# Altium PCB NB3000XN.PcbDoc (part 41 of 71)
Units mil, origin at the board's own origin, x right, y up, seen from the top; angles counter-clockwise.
Board outline 9527.56 x 6929.77 mil, 6 copper layers (Top Layer, GND+SHIELD, MidLayer1, MidLayer2, P2 - 3V3+5V0, Bottom Layer), stack 62.375 mil thick; 832 components, 1027 nets, 4655 pads, 4981 vias.
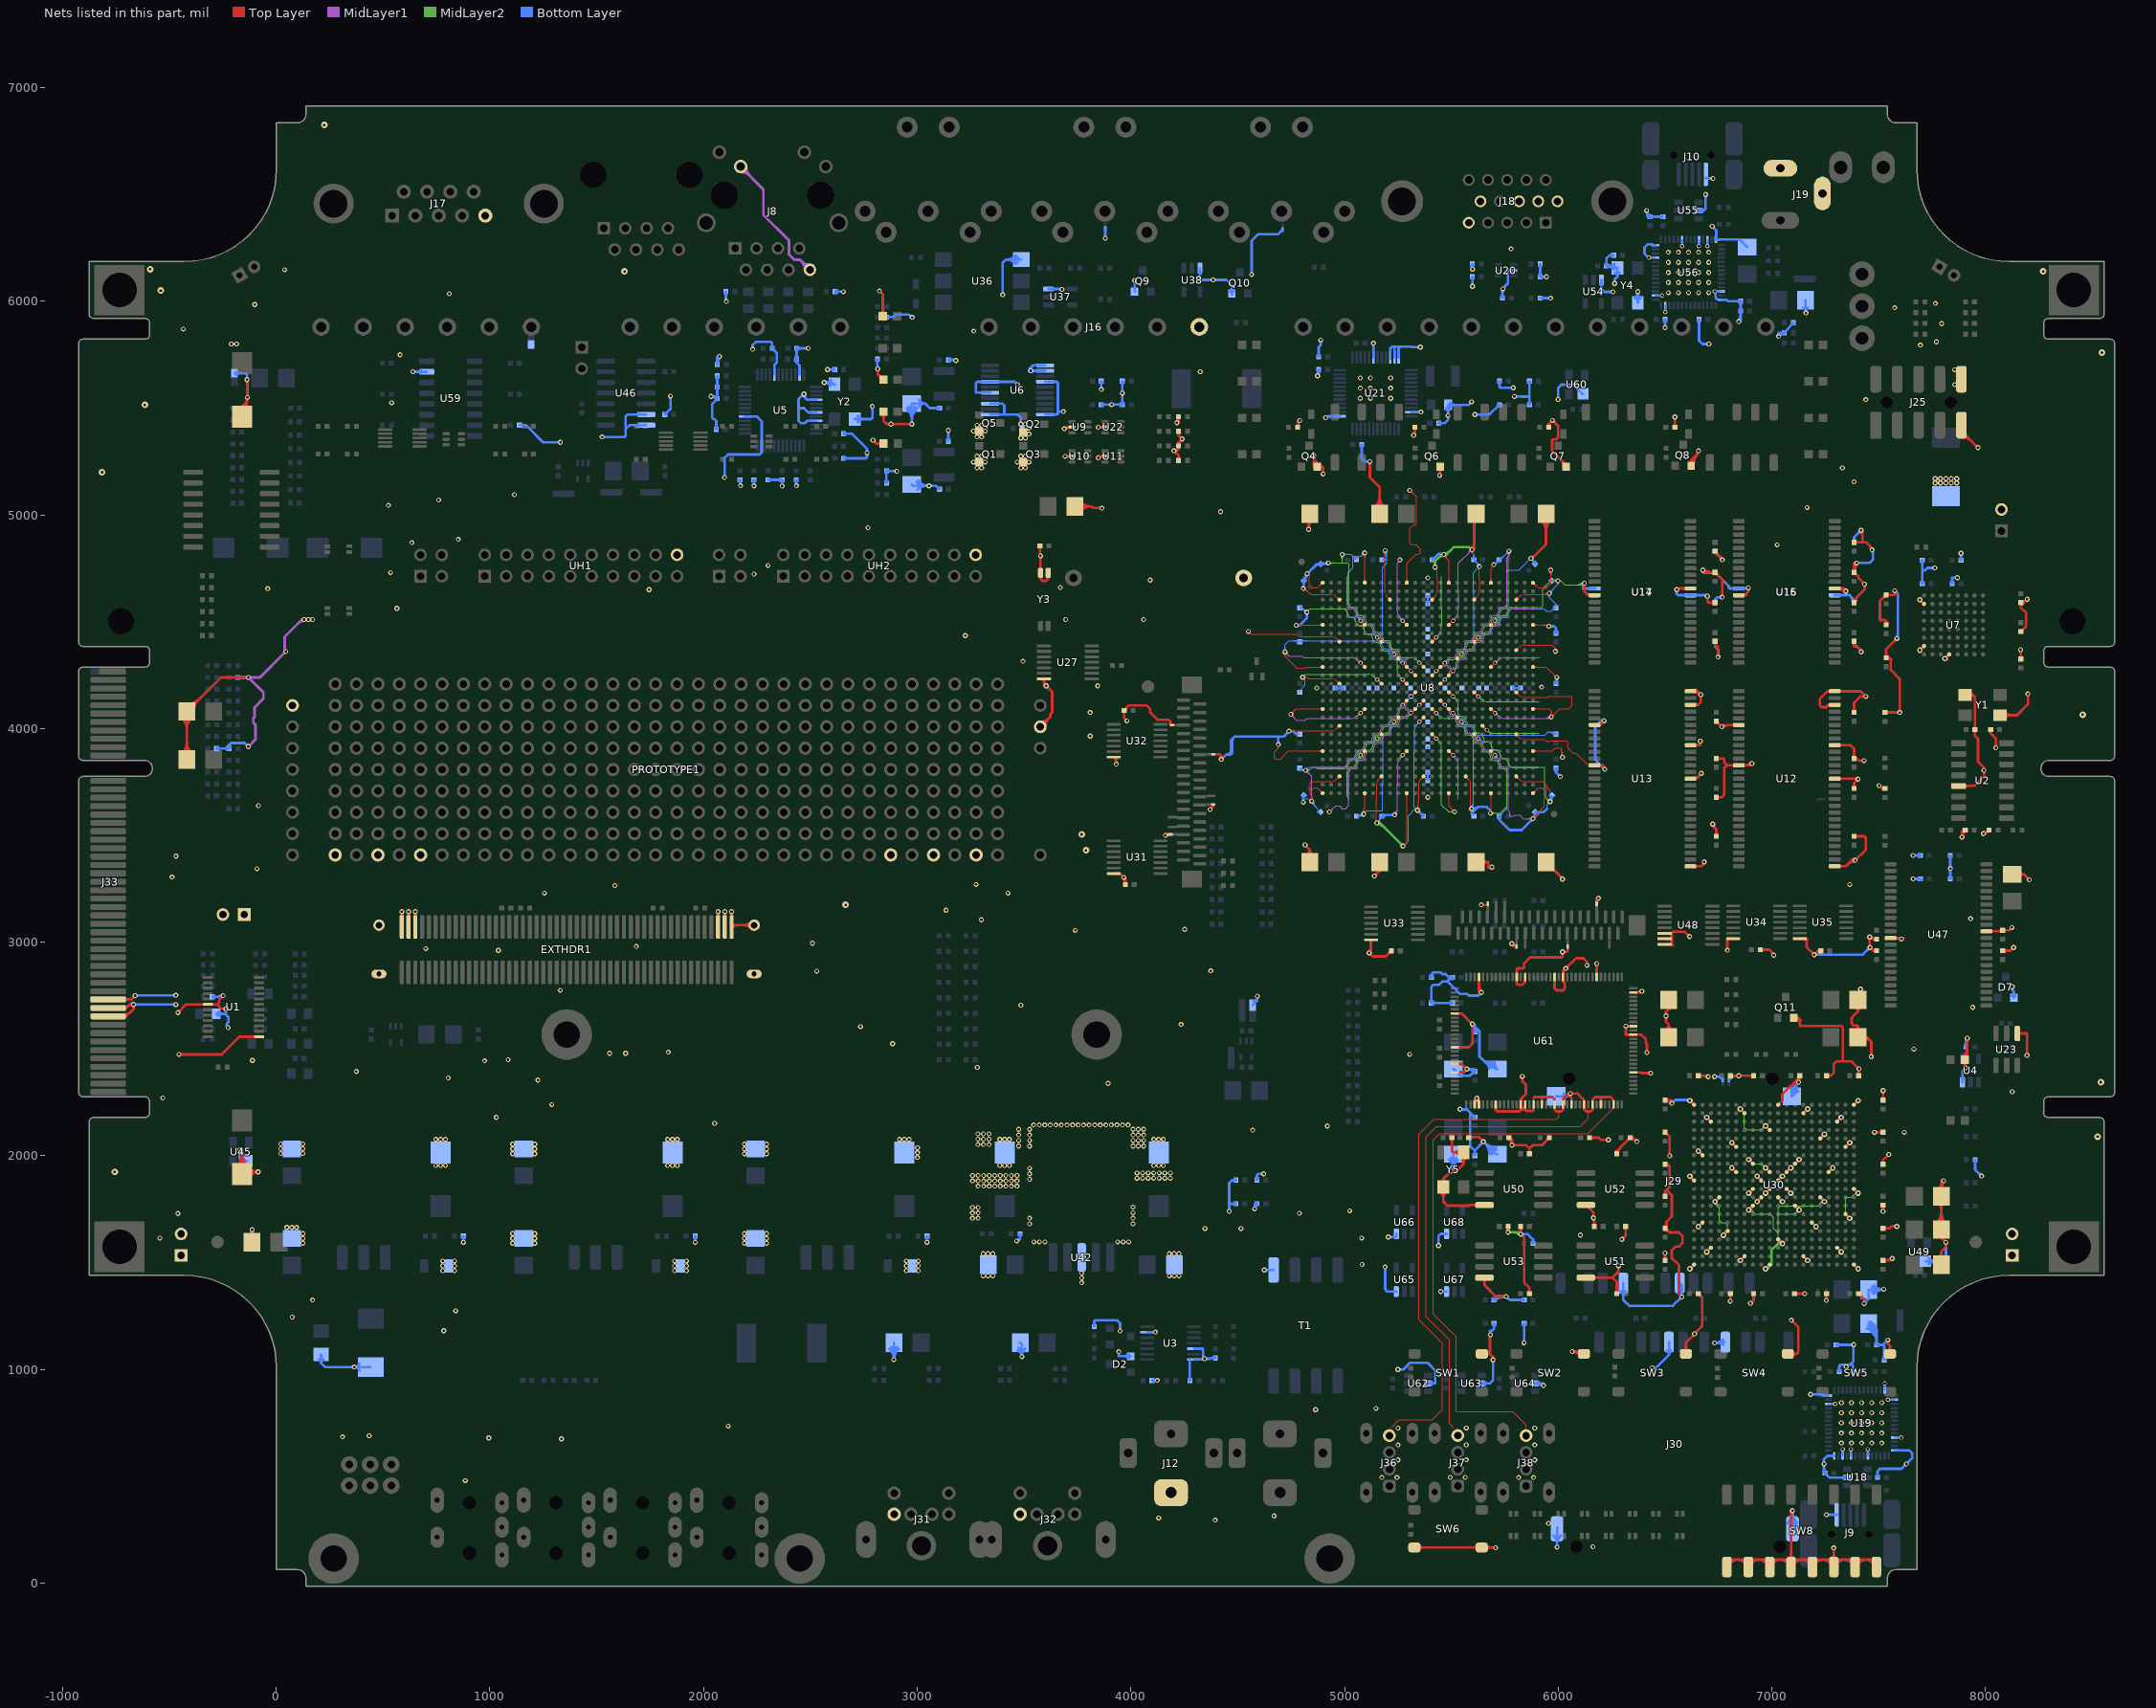
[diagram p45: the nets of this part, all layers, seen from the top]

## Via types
v1: diameter 23, hole 11.81, Top Layer to Bottom Layer, 3672 vias
v2: diameter 26, hole 11.81, Top Layer to Bottom Layer, 461 vias
v3: diameter 19, hole 11.81, Top Layer to Bottom Layer, tented both sides, 396 vias
v4: diameter 23.62, hole 11.81, Top Layer to Bottom Layer, 288 vias
v5: diameter 20, hole 11.81, Top Layer to Bottom Layer, 91 vias
v6: diameter 23, hole 11.81, Top Layer to Bottom Layer, tented both sides, 50 vias
v7: diameter 31, hole 11.81, Top Layer to Bottom Layer, 15 vias
v8: diameter 27.56, hole 11.81, Top Layer to Bottom Layer, tented both sides, 4 vias
v9: diameter 29, hole 11.81, Top Layer to Bottom Layer, 3 vias
v10: diameter 21, hole 11.81, Top Layer to Bottom Layer, 1 vias

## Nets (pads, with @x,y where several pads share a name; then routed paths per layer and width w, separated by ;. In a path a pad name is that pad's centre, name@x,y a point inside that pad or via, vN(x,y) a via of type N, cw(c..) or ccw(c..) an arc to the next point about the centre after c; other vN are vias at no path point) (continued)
GND: (continued)
  Top Layer w8: v2(6616.3,1471.3) U30.Y20@6635.98,1490.98 ; v2@6616.3,1480.3 ccw(c6616.3,1502.03) 6631.66,1486.66 ccw(c6647.03,1471.3) v2@6625.3,1471.3 ; v2@6616.3,1895.37 cw(c6616.3,1873.64) 6631.66,1889.01 cw(c6647.03,1904.37) v2@6625.3,1904.37 ; v2(6616.3,1904.37) U30.Y10@6635.98,1884.68 ; v2@6616.3,2249.7 cw(c6616.3,2227.97) 6631.66,2243.34 cw(c6647.03,2258.7) v2@6625.3,2258.7 ; v2(6616.3,2258.7) U30.Y1@6635.98,2239.02 ; U30.Y20@6630.14,1490.98 cw(c6616.04,1490.98) 6626.01,1481.01 cw(c6635.98,1471.04) U30.Y20@6635.98,1485.14 ; U30.Y10@6630.14,1884.68 ccw(c6616.04,1884.68) 6626.01,1894.66 ccw(c6635.98,1904.63) U30.Y10@6635.98,1890.53 ; U30.Y1@6630.14,2239.02 ccw(c6616.04,2239.02) 6626.01,2248.99 ccw(c6635.98,2258.96) U30.Y1@6635.98,2244.86 ; v2(6655.67,1668.15) U30.W15@6675.35,1687.83 ; v2@6655.67,1677.15 ccw(c6655.67,1698.88) 6671.03,1683.51 ccw(c6686.4,1668.15) v2@6664.67,1668.15 ; v2@6655.67,2013.48 cw(c6655.67,1991.75) 6671.03,2007.12 cw(c6686.4,2022.48) v2@6664.67,2022.48 ; v2(6655.67,2022.48) U30.W7@6675.35,2002.8 ; U30.W15@6669.51,1687.83 cw(c6655.41,1687.83) 6665.38,1677.86 cw(c6675.35,1667.89) U30.W15@6675.35,1681.99 ; U30.W7@6669.51,2002.8 ccw(c6655.41,2002.8) 6665.38,2012.77 ccw(c6675.35,2022.74) U30.W7@6675.35,2008.64 ; v2(6695.04,1550.04) U30.V18@6714.72,1569.72 ; v2@6695.04,1559.04 ccw(c6695.04,1580.77) 6710.4,1565.4 ccw(c6725.77,1550.04) v2@6704.04,1550.04 ; v2@6695.04,2170.96 cw(c6695.04,2149.23) 6710.4,2164.6 cw(c6725.77,2179.96) v2@6704.04,2179.96 ; v2(6695.04,2179.96) U30.V3@6714.72,2160.28 ; U30.V18@6708.88,1569.72 cw(c6694.78,1569.72) 6704.75,1559.75 cw(c6714.72,1549.78) U30.V18@6714.72,1563.88 ; U30.V3@6708.88,2160.28 ccw(c6694.78,2160.28) 6704.75,2170.25 ccw(c6714.72,2180.22) U30.V3@6714.72,2166.12 ; v2(6734.41,1786.26) U30.U12@6754.09,1805.94 ; v2@6734.41,1795.26 ccw(c6734.41,1816.99) 6749.77,1801.62 ccw(c6765.14,1786.26) v2@6743.41,1786.26 ; U30.U12@6748.25,1805.94 cw(c6734.15,1805.94) 6744.12,1795.97 cw(c6754.09,1786) U30.U12@6754.09,1800.1 ; v2(6773.78,1628.78) U30.T16@6793.46,1648.46 ; v2@6773.78,1637.78 ccw(c6773.78,1659.51) 6789.14,1644.14 ccw(c6804.51,1628.78) v2@6782.78,1628.78 ; U30.T16@6787.62,1648.46 cw(c6773.52,1648.46) 6783.49,1638.49 cw(c6793.46,1628.52) U30.T16@6793.46,1642.62 ; v2@6813.15,1934.74 cw(c6813.15,1913.01) 6828.51,1928.38 cw(c6843.88,1943.74) v2@6822.15,1943.74 ; v2(6813.15,1943.74) U30.R9@6832.83,1924.06 ; v2@6813.15,2052.85 cw(c6813.15,2031.12) 6828.51,2046.49 cw(c6843.88,2061.85) v2@6822.15,2061.85 ; v2(6813.15,2061.85) U30.R6@6832.83,2042.17 ; U30.R9@6826.99,1924.06 ccw(c6812.89,1924.06) 6822.86,1934.03 ccw(c6832.83,1944) U30.R9@6832.83,1929.9 ; U30.R6@6826.99,2042.17 ccw(c6812.89,2042.17) 6822.86,2052.14 ccw(c6832.83,2062.11) U30.R6@6832.83,2048.01 ; v2(6852.52,1510.67) U30.P19@6872.2,1530.35 ; v2@6852.52,1519.67 ccw(c6852.52,1541.4) 6867.88,1526.03 ccw(c6883.25,1510.67) v2@6861.52,1510.67 ; v2@6852.52,2210.33 cw(c6852.52,2188.6) 6867.88,2203.97 cw(c6883.25,2219.33) v2@6861.52,2219.33 ; v2(6852.52,2219.33) U30.P2@6872.2,2199.65 ; U30.P19@6866.36,1530.35 cw(c6852.26,1530.35) 6862.23,1520.38 cw(c6872.2,1510.41) U30.P19@6872.2,1524.51 ; U30.P2@6866.36,2199.65 ccw(c6852.26,2199.65) 6862.23,2209.62 ccw(c6872.2,2219.59) U30.P2@6872.2,2205.49 ; v2(6891.89,1746.89) U30.N13@6911.57,1766.57 ; v2@6891.89,1755.89 ccw(c6891.89,1777.62) 6907.25,1762.25 ccw(c6922.62,1746.89) v2@6900.89,1746.89 ; v2(6891.89,1825.63) U30.N11@6911.57,1845.31 ; v2@6891.89,1834.63 ccw(c6891.89,1856.36) 6907.25,1840.99 ccw(c6922.62,1825.63) v2@6900.89,1825.63 ; v2@6891.89,1974.11 cw(c6891.89,1952.38) 6907.25,1967.75 cw(c6922.62,1983.11) v2@6900.89,1983.11 ; v2(6891.89,1983.11) U30.N8@6911.57,1963.43 ; U30.N13@6905.73,1766.57 cw(c6891.63,1766.57) 6901.6,1756.6 cw(c6911.57,1746.63) U30.N13@6911.57,1760.73 ; U30.N11@6905.73,1845.31 cw(c6891.63,1845.31) 6901.6,1835.34 cw(c6911.57,1825.37) U30.N11@6911.57,1839.47 ; U30.N8@6905.73,1963.43 ccw(c6891.63,1963.43) 6901.6,1973.4 ccw(c6911.57,1983.37) U30.N8@6911.57,1969.27 ; v2(6931.26,1786.26) U30.M12@6950.94,1805.94 ; v2@6931.26,1795.26 ccw(c6931.26,1816.99) 6946.62,1801.62 ccw(c6961.99,1786.26) v2@6940.26,1786.26 ; v2@6931.26,1895.37 cw(c6931.26,1873.64) 6946.62,1889.01 cw(c6961.99,1904.37) v2@6940.26,1904.37 ; v2(6931.26,1904.37) U30.M10@6950.94,1884.68 ; U30.M12@6945.1,1805.94 cw(c6931,1805.94) 6940.97,1795.97 cw(c6950.94,1786) U30.M12@6950.94,1800.1 ; U30.M10@6945.1,1884.68 ccw(c6931,1884.68) 6940.97,1894.66 ccw(c6950.94,1904.63) U30.M10@6950.94,1890.53 ; v2(6970.63,1471.3) U30.L20@6990.31,1490.98 ; v2@6970.63,1480.3 ccw(c6970.63,1502.03) 6985.99,1486.66 ccw(c7001.36,1471.3) v2@6979.63,1471.3 ; v2(6970.63,1825.63) U30.L11@6990.31,1845.31 ; v2@6970.63,1834.63 ccw(c6970.63,1856.36) 6985.99,1840.99 ccw(c7001.36,1825.63) v2@6979.63,1825.63 ; v2@6970.63,1934.74 cw(c6970.63,1913.01) 6985.99,1928.38 cw(c7001.36,1943.74) v2@6979.63,1943.74 ; v2(6970.63,1943.74) U30.L9@6990.31,1924.06 ; v2@6970.63,2131.59 cw(c6970.63,2109.86) 6985.99,2125.23 cw(c7001.36,2140.59) v2@6979.63,2140.59 ; v2(6970.63,2140.59) U30.L4@6990.31,2120.91 ; U30.L20@6984.47,1490.98 cw(c6970.37,1490.98) 6980.34,1481.01 cw(c6990.31,1471.04) U30.L20@6990.31,1485.14 ; U30.L11@6984.47,1845.31 cw(c6970.37,1845.31) 6980.34,1835.34 cw(c6990.31,1825.37) U30.L11@6990.31,1839.47 ; U30.L9@6984.47,1924.06 ccw(c6970.37,1924.06) 6980.34,1934.03 ccw(c6990.31,1944) U30.L9@6990.31,1929.9 ; U30.L4@6984.47,2120.91 ccw(c6970.37,2120.91) 6980.34,2130.88 ccw(c6990.31,2140.85) U30.L4@6990.31,2126.75 ; U30.K17@7029.69,1603.25 cw(c7029.69,1589.15) 7039.66,1599.12 cw(c7049.63,1609.09) U30.K17@7035.53,1609.09 ; U30.K17@7029.69,1609.09 v2(7049.37,1589.41) ; U30.K12@7029.69,1800.1 cw(c7029.69,1786) 7039.66,1795.97 cw(c7049.63,1805.94) U30.K12@7035.53,1805.94 ; U30.K12@7029.69,1805.94 v2(7049.37,1786.26) ; U30.K10@7029.69,1884.68 v2(7049.37,1904.37) ; U30.K10@7029.69,1890.53 ccw(c7029.69,1904.63) 7039.66,1894.66 ccw(c7049.63,1884.68) U30.K10@7035.53,1884.68 ; U30.K1@7029.69,2239.02 7049.37,2258.7 ; U30.K1@7029.69,2244.86 ccw(c7029.69,2258.96) 7039.66,2248.99 ccw(c7049.63,2239.02) U30.K1@7035.53,2239.02 ; v2@7040.37,1589.41 ccw(c7018.64,1589.41) 7034.01,1604.77 ccw(c7049.37,1620.14) v2@7049.37,1598.41 ; v2@7040.37,1786.26 ccw(c7018.64,1786.26) 7034.01,1801.62 ccw(c7049.37,1816.99) v2@7049.37,1795.26 ; v2@7040.37,1904.37 cw(c7018.64,1904.37) 7034.01,1889.01 cw(c7049.37,1873.64) v2@7049.37,1895.37 ; U30.J11@7069.06,1839.47 cw(c7069.06,1825.37) 7079.03,1835.34 cw(c7089,1845.31) U30.J11@7074.9,1845.31 ; U30.J11@7069.06,1845.31 v2(7088.74,1825.63) ; U30.J9@7069.06,1924.06 v2(7088.74,1943.74) ; U30.J9@7069.06,1929.9 ccw(c7069.06,1944) 7079.03,1934.03 ccw(c7089,1924.06) U30.J9@7074.9,1924.06 ; v2@7079.74,1825.63 ccw(c7058.01,1825.63) 7073.38,1840.99 ccw(c7088.74,1856.36) v2@7088.74,1834.63 ; v2@7079.74,1943.74 cw(c7058.01,1943.74) 7073.38,1928.38 cw(c7088.74,1913.01) v2@7088.74,1934.74 ; U30.H13@7108.43,1760.73 cw(c7108.43,1746.63) 7118.4,1756.6 cw(c7128.37,1766.57) U30.H13@7114.27,1766.57 ; U30.H13@7108.43,1766.57 v2(7128.11,1746.89) ; U30.H8@7108.43,1963.43 v2(7128.11,1983.11) ; U30.H8@7108.43,1969.27 ccw(c7108.43,1983.37) 7118.4,1973.4 ccw(c7128.37,1963.43) U30.H8@7114.27,1963.43 ; v2@7119.11,1746.89 ccw(c7097.38,1746.89) 7112.75,1762.25 ccw(c7128.11,1777.62) v2@7128.11,1755.89 ; v2@7119.11,1983.11 cw(c7097.38,1983.11) 7112.75,1967.75 cw(c7128.11,1952.38) v2@7128.11,1974.11 ; U30.G19@7147.8,1524.51 cw(c7147.8,1510.41) 7157.77,1520.38 cw(c7167.74,1530.35) U30.G19@7153.64,1530.35 ; U30.G19@7147.8,1530.35 v2(7167.48,1510.67) ; U30.G2@7147.8,2199.65 v2(7167.48,2219.33) ; U30.G2@7147.8,2205.49 ccw(c7147.8,2219.59) 7157.77,2209.62 ccw(c7167.74,2199.65) U30.G2@7153.64,2199.65 ; v2@7158.48,1510.67 ccw(c7136.75,1510.67) 7152.12,1526.03 ccw(c7167.48,1541.4) v2@7167.48,1519.67 ; v2@7158.48,2219.33 cw(c7136.75,2219.33) 7152.12,2203.97 cw(c7167.48,2188.6) v2@7167.48,2210.33 ; U30.F15@7187.17,1681.99 cw(c7187.17,1667.89) 7197.14,1677.86 cw(c7207.11,1687.83) U30.F15@7193.01,1687.83 ; U30.F15@7187.17,1687.83 v2(7206.85,1668.15) ; v2@7197.85,1668.15 ccw(c7176.12,1668.15) 7191.49,1683.51 ccw(c7206.85,1698.88) v2@7206.85,1677.15 ; U30.E12@7226.54,1800.1 cw(c7226.54,1786) 7236.51,1795.97 cw(c7246.48,1805.94) U30.E12@7232.38,1805.94 ; U30.E12@7226.54,1805.94 v2(7246.22,1786.26) ; U30.E5@7226.54,2081.54 v2(7246.22,2101.22) ; U30.E5@7226.54,2087.38 ccw(c7226.54,2101.48) 7236.51,2091.51 ccw(c7246.48,2081.54) U30.E5@7232.38,2081.54 ; v2@7237.22,1786.26 ccw(c7215.49,1786.26) 7230.86,1801.62 ccw(c7246.22,1816.99) v2@7246.22,1795.26 ; v2@7237.22,2101.22 cw(c7215.49,2101.22) 7230.86,2085.86 cw(c7246.22,2070.49) v2@7246.22,2092.22 ; U30.D9@7265.91,1924.06 v2(7285.59,1943.74) ; U30.D9@7265.91,1929.9 ccw(c7265.91,1944) 7275.88,1934.03 ccw(c7285.85,1924.06) U30.D9@7271.75,1924.06 ; v2@7276.59,1943.74 cw(c7254.86,1943.74) 7270.23,1928.38 cw(c7285.59,1913.01) v2@7285.59,1934.74 ; U30.C18@7305.28,1563.88 cw(c7305.28,1549.78) 7315.25,1559.75 cw(c7325.22,1569.72) U30.C18@7311.12,1569.72 ; U30.C18@7305.28,1569.72 v2(7324.96,1550.04) ; U30.C3@7305.28,2160.28 v2(7324.96,2179.96) ; U30.C3@7305.28,2166.12 ccw(c7305.28,2180.22) 7315.25,2170.25 ccw(c7325.22,2160.28) U30.C3@7311.12,2160.28 ; v2@7315.96,1550.04 ccw(c7294.23,1550.04) 7309.6,1565.4 ccw(c7324.96,1580.77) v2@7324.96,1559.04 ; v2@7315.96,2179.96 cw(c7294.23,2179.96) 7309.6,2164.6 cw(c7324.96,2149.23) v2@7324.96,2170.96 ; U30.B14@7344.65,1721.36 cw(c7344.65,1707.26) 7354.62,1717.23 cw(c7364.59,1727.2) U30.B14@7350.49,1727.2 ; U30.B14@7344.65,1727.2 v2(7364.33,1707.52) ; U30.B6@7344.65,2042.17 v2(7364.33,2061.85) ; U30.B6@7344.65,2048.01 ccw(c7344.65,2062.11) 7354.62,2052.14 ccw(c7364.59,2042.17) U30.B6@7350.49,2042.17 ; v2@7355.33,1707.52 ccw(c7333.6,1707.52) 7348.97,1722.88 ccw(c7364.33,1738.25) v2@7364.33,1716.52 ; v2@7355.33,2061.85 cw(c7333.6,2061.85) 7348.97,2046.49 cw(c7364.33,2031.12) v2@7364.33,2052.85 ; U30.A20@7384.02,1485.14 cw(c7384.02,1471.04) 7393.99,1481.01 cw(c7403.96,1490.98) U30.A20@7389.86,1490.98 ; U30.A20@7384.02,1490.98 v2(7403.7,1471.3) ; U30.A11@7384.02,1839.47 cw(c7384.02,1825.37) 7393.99,1835.34 cw(c7403.96,1845.31) U30.A11@7389.86,1845.31 ; U30.A11@7384.02,1845.31 v2(7403.7,1825.63) ; U30.A1@7384.02,2239.02 v2(7403.7,2258.7) ; U30.A1@7384.02,2244.86 ccw(c7384.02,2258.96) 7393.99,2248.99 ccw(c7403.96,2239.02) U30.A1@7389.86,2239.02 ; v2@7394.7,1471.3 ccw(c7372.97,1471.3) 7388.34,1486.66 ccw(c7403.7,1502.03) v2@7403.7,1480.3 ; v2@7394.7,1825.63 ccw(c7372.97,1825.63) 7388.34,1840.99 ccw(c7403.7,1856.36) v2@7403.7,1834.63 ; v2@7394.7,2258.7 cw(c7372.97,2258.7) 7388.34,2243.34 cw(c7403.7,2227.97) v2@7403.7,2249.7 ; v2(7692.52,4366.89) U7.H7@7712.2,4386.57 ; v2@7692.52,4375.89 ccw(c7692.52,4397.62) 7707.88,4382.25 ccw(c7723.25,4366.89) v2@7701.52,4366.89 ; v2@7692.52,4594.11 cw(c7692.52,4572.38) 7707.88,4587.75 cw(c7723.25,4603.11) v2@7701.52,4603.11 ; v2(7692.52,4603.11) U7.H2@7712.2,4583.43 ; U7.H7@7706.2,4386.57 cw(c7691.72,4386.57) 7701.96,4376.33 cw(c7712.2,4366.09) U7.H7@7712.2,4380.57 ; U7.H2@7706.2,4583.43 ccw(c7691.72,4583.43) 7701.96,4593.67 ccw(c7712.2,4603.91) U7.H2@7712.2,4589.43 ; v2(7810.63,4327.52) U7.E8@7830.32,4347.2 ; v2@7810.63,4336.52 ccw(c7810.63,4358.25) 7825.99,4342.88 ccw(c7841.36,4327.52) v2@7819.63,4327.52 ; U7.E8@7824.32,4347.2 cw(c7809.83,4347.2) 7820.07,4336.96 cw(c7830.32,4326.72) U7.E8@7830.32,4341.2
  Top Layer w11.81: v1@7539.57,1134.42 cw(c7530.02,1124.87) 7543.52,1124.87 cw(c7557.03,1124.87) v1@7547.48,1134.42 ; SW5.3@7541.89,1085.62 ccw(c7520.35,1110) 7552.87,1110 ccw(c7585.4,1110) SW5.3@7563.86,1085.62 ; v1(7543.52,1138.37) 7543.52,1119.35 7552.87,1110 SW5.3@7552.87,1073.19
